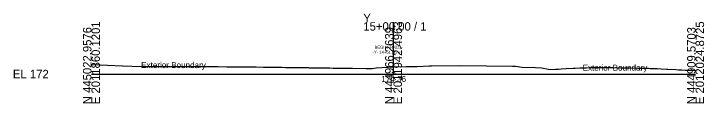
# Model space of a CAD drawing. Extents: x -26 to 3203, y -10 to 9532.
# Drawn here: x -25.7 to 202.8, y 8990.3 to 9020 of the extents above; entities that cross this region are included whole.
import ezdxf

# ---------------------------------------------------------------- set-up
doc = ezdxf.new("R2010")
doc.units = 0
for name, color, linetype in [('Default', 7, 'Continuous'), ('Exist Cross Section Cell', 7, 'Continuous'), ('Exist XS Center Line Elevation Label', 7, 'Continuous'), ('Exist XS Ground Line', 7, 'Continuous'), ('Prop XS SE Text', 7, 'Continuous'), ('Scratch_Level_0', 7, 'Continuous')]:
    doc.layers.add(name, color=color, linetype=linetype)

msp = doc.modelspace()

# ---------------------------------------------------------------- linework, layer by layer
at = {"layer": 'Exist Cross Section Cell'}
for p, q in [((100, 9000), (100, 9017.22)), ((0, 9000), (100, 9000)), ((100, 9000), (200, 9000))]:
    msp.add_line(p, q, dxfattribs=at)
at = {"layer": 'Exist XS Ground Line'}
msp.add_lwpolyline([(0, 9003.17), (2.84, 9003.03), (5.33, 9002.91), (10.29, 9002.72), (16.57, 9002.49), (17.56, 9002.49), (18.03, 9002.48), (18.84, 9002.48), (20.99, 9002.49), (22.78, 9002.49), (23.56, 9002.5), (25.04, 9002.5), (26.59, 9002.5), (27.19, 9002.5), (28.61, 9002.5), (29.59, 9002.51), (31.58, 9002.51), (32.66, 9002.51), (34.02, 9002.49), (35.97, 9002.48), (37.62, 9002.48), (38.93, 9002.48), (39.52, 9002.49), (40.43, 9002.49), (41.96, 9002.47), (44.84, 9002.43), (47.83, 9002.42), (49.25, 9002.41), (50.2, 9002.4), (50.86, 9002.39), (51.99, 9002.38), (53.9, 9002.36), (54.49, 9002.35), (56.93, 9002.31), (57.37, 9002.31), (58, 9002.29), (59.63, 9002.28), (61.84, 9002.27), (62.32, 9002.26), (63, 9002.25), (64.25, 9002.21), (66.18, 9002.17), (66.79, 9002.15), (68.15, 9002.15), (69.06, 9002.14), (71.17, 9002.13), (71.73, 9002.12), (72.11, 9002.11), (73.53, 9002.07), (75.63, 9002.03), (78.17, 9002.01), (78.91, 9002.01), (80, 9001.99), (80.91, 9001.99), (83.01, 9001.97), (83.85, 9001.95), (84.71, 9001.94), (86.44, 9001.9), (90.99, 9001.89), (92.96, 9001.87), (94.29, 9002.03), (98.13, 9002.31), (100, 9002.36), (104.23, 9002.46), (107.56, 9002.54), (107.87, 9002.55), (111.92, 9002.73), (112.62, 9002.76), (121.77, 9002.89), (130.77, 9002.74), (139.43, 9002.65), (140.33, 9002.57), (142.56, 9002.25), (147.01, 9002.15), (149.03, 9002.07), (151.25, 9001.67), (152.03, 9001.53), (153.57, 9001.61), (154.61, 9001.67), (155.51, 9001.74), (157.11, 9001.87), (159.46, 9001.97), (160.15, 9002), (161.66, 9002.04), (163.47, 9002.08), (163.88, 9002.09), (165.25, 9002.12), (166.18, 9002.13), (167.05, 9002.15), (168.3, 9002.18), (168.85, 9002.19), (169.17, 9002.19), (170.65, 9002.21), (171.94, 9002.16), (172.7, 9002.14), (175.29, 9002.1), (177.09, 9002.07), (178.31, 9002.04), (180.96, 9002), (181.45, 9001.99), (182.95, 9001.96), (184.37, 9001.91), (185, 9001.89), (185.89, 9001.85), (187.4, 9001.79), (188.59, 9001.74), (190.46, 9001.64), (190.81, 9001.62), (193.46, 9001.46), (194.3, 9001.42), (195.28, 9001.37), (196.66, 9001.28), (197.06, 9001.25), (197.44, 9001.24), (200, 9001.19)], dxfattribs=at)

# ---------------------------------------------------------------- texts
at = {"layer": 'Default'}
msp.add_text('-', height=0.0001, dxfattribs=at).set_placement((0, 9000))
at = {"layer": 'Exist Cross Section Cell'}
for s, p in [('Y', (90, 9017.22)), ('15+00.00 / 1', (90, 9014.42)), ('EL 172', (-26, 8998.6))]:
    msp.add_text(s, height=2.8, dxfattribs=at).set_placement(p)
for s, p in [('E 2011860.1201', (2.8, 8990)), ('E 2011942.4963', (102.8, 8990)), ('E 2012024.8725', (202.8, 8990)), ('N 445022.9576', (0, 8990)), ('N 444966.2639', (100, 8990)), ('N 444909.5703', (200, 8990))]:
    msp.add_text(s, height=2.8, rotation=90, dxfattribs=at).set_placement(p)
at = {"layer": 'Exist XS Center Line Elevation Label'}
msp.add_text('174.36', height=2, dxfattribs=at).set_placement((95.97, 8997.36))
at = {"layer": 'Prop XS SE Text'}
for s, p in [('BEGIN -RND1-', (93.72, 9008.38)), ('-Y- 14+51.65+/-', (93.07, 9006.76))]:
    msp.add_text(s, height=1, dxfattribs=at).set_placement(p)
at = {"layer": 'Scratch_Level_0'}
for p in [(16.45, 9001.97), (162.6, 9001.12)]:
    msp.add_text('Exterior Boundary', height=2, dxfattribs=at).set_placement(p)

doc.saveas('drawing.dxf')
